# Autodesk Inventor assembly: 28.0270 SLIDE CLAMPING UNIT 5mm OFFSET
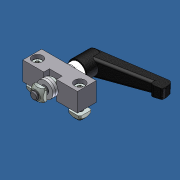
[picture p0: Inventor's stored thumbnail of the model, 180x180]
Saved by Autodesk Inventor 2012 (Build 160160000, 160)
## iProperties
Created: 2007-06
Part Number: 28.0270 SLIDE CLAMPING UNIT 5mm OFFSET
Document SubType Name: Assembly
Designer: Andy Moles
Vendor: V
Author: Andy Moles
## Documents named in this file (8)
- C:\Andys Backup Data\ANDY'S INVENTOR\INVENTOR LIBRARIES\PARTS LIBRARY\COMPONENTS LR\SUBCOMPONENTS\28.0270 SLIDE CLAMPING UNIT 5mm OFFSET.iam
- C:\Andys Backup Data\ANDY'S INVENTOR\INVENTOR LIBRARIES\PARTS LIBRARY\COMPONENTS LR\SUBCOMPONENTS\28.0270 SLIDE CLAMPING UNIT AL BLOCK.ipt
- C:\Andys Backup Data\ANDY'S INVENTOR\INVENTOR LIBRARIES\PARTS LIBRARY\FASTENING ELEMENTS\SCREWS CAP\21.1242 M6X25.ipt
- C:\Andys Backup Data\ANDY'S INVENTOR\INVENTOR LIBRARIES\PARTS LIBRARY\FASTENING ELEMENTS\NUTS\21.1330 M6 SQUARE NUT.ipt
- C:\Andys Backup Data\ANDY'S INVENTOR\INVENTOR LIBRARIES\PARTS LIBRARY\FASTENING ELEMENTS\WASHERS\WASHER M8 PLASTIC 17mm OD.ipt
- C:\Andys Backup Data\ANDY'S INVENTOR\INVENTOR LIBRARIES\PARTS LIBRARY\COMPONENTS LR\SUBCOMPONENTS\28.0270 SLIDE CLAMPING UNIT HANDLE.ipt
- C:\Andys Backup Data\ANDY'S INVENTOR\INVENTOR LIBRARIES\PARTS LIBRARY\COMPONENTS LR\SUBCOMPONENTS\28.0271 THREADED STUD.ipt
- C:\Andys Backup Data\ANDY'S INVENTOR\INVENTOR LIBRARIES\PARTS LIBRARY\FASTENING ELEMENTS\NUTS\21.1351 M8 SQUARE NUT.ipt
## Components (12 placed, 7 different names)
1. 28.0270 SLIDE CLAMPING UNIT AL BLOCK:1 — Insert:1, Insert:2, Insert:3, Insert:4, Insert:5, Angle:1, Angle:2
2. 21.1242 M6 x 25 SHCS:1 — Insert:1
3. 21.1242 M6 x 25 SHCS:2 — Insert:2
4. 21.1330 M6 SQUARE NUT:1 — Insert:4
5. 21.1330 M6 SQUARE NUT:2 — Insert:3
6. WASHER M8 PLASTIC 17mm OD:1 — Insert:5, Insert:12, Mate:7
7. WASHER M8 PLASTIC 17mm OD:3 — Mate:2, Insert:10, Insert:13
8. 28.0270 SLIDE CLAMPING UNIT HANDLE:1 — Insert:12, Mate:8
9. 28.0271 THREADED STUD:1 — Mate:1, Mate:5, Mate:7, Mate:8
10. 21.1351 M8 SQUARE NUT:1 — Mate:1, Angle:1, Mate:6
11. 21.1351 M8 SQUARE NUT:2 — Insert:10, Angle:2
12. WASHER M8 PLASTIC 17mm OD:4 — Insert:13, Mate:5, Mate:6
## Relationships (16: Insert 8, Mate 6, Angle 2)
- Insert:1: 28.0270 SLIDE CLAMPING UNIT AL BLOCK:1 ↔ 21.1242 M6 x 25 SHCS:1
- Insert:2: 28.0270 SLIDE CLAMPING UNIT AL BLOCK:1 ↔ 21.1242 M6 x 25 SHCS:2
- Insert:3: 28.0270 SLIDE CLAMPING UNIT AL BLOCK:1 ↔ 21.1330 M6 SQUARE NUT:2
- Insert:4: 28.0270 SLIDE CLAMPING UNIT AL BLOCK:1 ↔ 21.1330 M6 SQUARE NUT:1
- Insert:5: 28.0270 SLIDE CLAMPING UNIT AL BLOCK:1 ↔ WASHER M8 PLASTIC 17mm OD:1
- Mate:1: 28.0271 THREADED STUD:1 ↔ 21.1351 M8 SQUARE NUT:1
- Mate:2: WASHER M8 PLASTIC 17mm OD:3
- Insert:10: WASHER M8 PLASTIC 17mm OD:3 ↔ 21.1351 M8 SQUARE NUT:2
- Insert:12: WASHER M8 PLASTIC 17mm OD:1 ↔ 28.0270 SLIDE CLAMPING UNIT HANDLE:1
- Angle:1: 28.0270 SLIDE CLAMPING UNIT AL BLOCK:1 ↔ 21.1351 M8 SQUARE NUT:1
- Insert:13: WASHER M8 PLASTIC 17mm OD:3 ↔ WASHER M8 PLASTIC 17mm OD:4
- Angle:2: 28.0270 SLIDE CLAMPING UNIT AL BLOCK:1 ↔ 21.1351 M8 SQUARE NUT:2
- Mate:5: 28.0271 THREADED STUD:1 ↔ WASHER M8 PLASTIC 17mm OD:4
- Mate:6: 21.1351 M8 SQUARE NUT:1 ↔ WASHER M8 PLASTIC 17mm OD:4
- Mate:7: WASHER M8 PLASTIC 17mm OD:1 ↔ 28.0271 THREADED STUD:1
- Mate:8: 28.0270 SLIDE CLAMPING UNIT HANDLE:1 ↔ 28.0271 THREADED STUD:1
